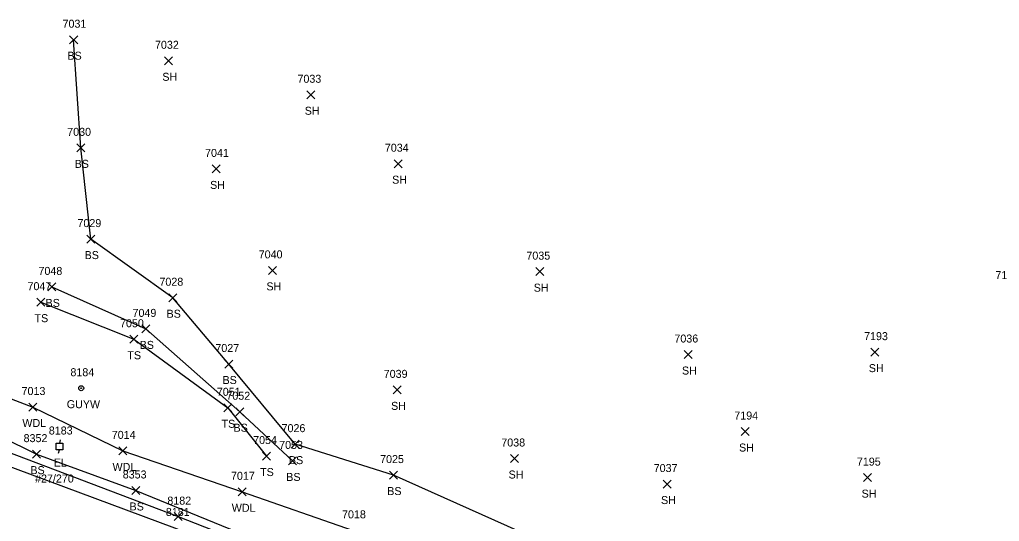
# Model space of a CAD drawing. Extents: x 1588028 to 1589597, y 137576 to 138176.
# Drawn here: x 1589205.2 to 1589450, y 137792.6 to 137918 of the extents above; entities that cross this region are included whole.
import ezdxf

# ---------------------------------------------------------------- set-up
doc = ezdxf.new("R2010")
doc.units = 0
for name, color, linetype in [('L_A', 7, 'Continuous'), ('L_I', 7, 'Continuous'), ('L_TIC', 7, 'Continuous'), ('LAWA', 7, 'Continuous'), ('LELB', 7, 'Continuous'), ('P_I', 7, 'Continuous'), ('P_TIC', 7, 'Continuous'), ('PET', 7, 'Continuous'), ('PSU', 7, 'Continuous'), ('U_A', 7, 'Continuous'), ('U_C', 7, 'Continuous'), ('U_I', 7, 'Continuous'), ('UEPT', 7, 'Continuous'), ('UPGW', 7, 'Continuous')]:
    doc.layers.add(name, color=color, linetype=linetype)

msp = doc.modelspace()

# ---------------------------------------------------------------- linework, layer by layer
at = {"layer": 'L_TIC'}
for points in [[(1589217.71, 137912.01), (1589219.71, 137914.01)], [(1589219.71, 137912.01), (1589217.71, 137914.01)], [(1589241.37, 137906.74), (1589243.37, 137908.74)], [(1589243.37, 137906.74), (1589241.37, 137908.74)], [(1589276.97, 137898.25), (1589278.97, 137900.25)], [(1589278.97, 137898.25), (1589276.97, 137900.25)], [(1589219.52, 137884.98), (1589221.52, 137886.98)], [(1589221.52, 137884.98), (1589219.52, 137886.98)], [(1589253.31, 137879.71), (1589255.31, 137881.71)], [(1589255.31, 137879.71), (1589253.31, 137881.71)], [(1589298.8, 137881.01), (1589300.8, 137883.01)], [(1589300.8, 137881.01), (1589298.8, 137883.01)], [(1589222.01, 137862.17), (1589224.01, 137864.17)], [(1589224.01, 137862.17), (1589222.01, 137864.17)], [(1589267.38, 137854.35), (1589269.38, 137856.35)], [(1589269.38, 137854.35), (1589267.38, 137856.35)], [(1589334.17, 137854.03), (1589336.17, 137856.03)], [(1589336.17, 137854.03), (1589334.17, 137856.03)], [(1589212.25, 137850.21), (1589214.25, 137852.21)], [(1589214.25, 137850.21), (1589212.25, 137852.21)], [(1589242.48, 137847.51), (1589244.48, 137849.51)], [(1589244.48, 137847.51), (1589242.48, 137849.51)], [(1589209.52, 137846.4), (1589211.52, 137848.4)], [(1589211.52, 137846.4), (1589209.52, 137848.4)], [(1589235.77, 137839.72), (1589237.77, 137841.72)], [(1589237.77, 137839.72), (1589235.77, 137841.72)], [(1589232.72, 137837.13), (1589234.72, 137839.13)], [(1589234.72, 137837.13), (1589232.72, 137839.13)], [(1589371.21, 137833.31), (1589373.21, 137835.31)], [(1589373.21, 137833.31), (1589371.21, 137835.31)], [(1589417.9, 137833.91), (1589419.9, 137835.91)], [(1589419.9, 137833.91), (1589417.9, 137835.91)], [(1589256.46, 137830.94), (1589258.46, 137832.94)], [(1589258.46, 137830.94), (1589256.46, 137832.94)], [(1589298.53, 137824.48), (1589300.53, 137826.48)], [(1589300.53, 137824.48), (1589298.53, 137826.48)], [(1589207.47, 137820.19), (1589209.47, 137822.19)], [(1589209.47, 137820.19), (1589207.47, 137822.19)], [(1589256.26, 137820), (1589258.26, 137822)], [(1589258.26, 137820), (1589256.26, 137822)], [(1589259.21, 137819.01), (1589261.21, 137821.01)], [(1589261.21, 137819.01), (1589259.21, 137821.01)], [(1589385.47, 137814.06), (1589387.47, 137816.06)], [(1589387.47, 137814.06), (1589385.47, 137816.06)], [(1589273.05, 137810.91), (1589275.05, 137812.91)], [(1589275.05, 137810.91), (1589273.05, 137812.91)], [(1589208.46, 137808.41), (1589210.46, 137810.41)], [(1589210.46, 137808.41), (1589208.46, 137810.41)], [(1589230.01, 137809.22), (1589232.01, 137811.22)], [(1589232.01, 137809.22), (1589230.01, 137811.22)], [(1589265.88, 137807.93), (1589267.88, 137809.93)], [(1589267.88, 137807.93), (1589265.88, 137809.93)], [(1589272.39, 137806.71), (1589274.39, 137808.71)], [(1589274.39, 137806.71), (1589272.39, 137808.71)], [(1589327.89, 137807.32), (1589329.89, 137809.32)], [(1589329.89, 137807.32), (1589327.89, 137809.32)], [(1589297.62, 137803.18), (1589299.62, 137805.18)], [(1589299.62, 137803.18), (1589297.62, 137805.18)], [(1589365.97, 137800.93), (1589367.97, 137802.93)], [(1589367.97, 137800.93), (1589365.97, 137802.93)], [(1589416.1, 137802.54), (1589418.1, 137804.54)], [(1589418.1, 137802.54), (1589416.1, 137804.54)], [(1589233.23, 137799.33), (1589235.23, 137801.33)], [(1589235.23, 137799.33), (1589233.23, 137801.33)], [(1589259.79, 137798.99), (1589261.79, 137800.99)], [(1589261.79, 137798.99), (1589259.79, 137800.99)]]:
    msp.add_lwpolyline(points, dxfattribs=at)
at = {"layer": 'LAWA'}
msp.add_lwpolyline([(1589191.48, 137827.66), (1589208.47, 137821.19), (1589231.01, 137810.22), (1589260.79, 137799.99), (1589288.54, 137790.36), (1589312.49, 137778.55), (1589337.68, 137767.31), (1589356.85, 137760.89), (1589388.23, 137746.7), (1589420.91, 137733.88), (1589453.12, 137717.84), (1589474.94, 137709.38)], dxfattribs=at)
at = {"layer": 'LELB'}
for points in [[(1589363.98, 137776.23), (1589339.81, 137785.78), (1589298.62, 137804.18), (1589274.05, 137811.91), (1589257.46, 137831.94), (1589243.48, 137848.51), (1589223.01, 137863.17), (1589220.52, 137885.98), (1589218.71, 137913.01)], [(1589213.25, 137851.21), (1589236.77, 137840.72), (1589260.21, 137820.01), (1589273.39, 137807.71)], [(1589210.52, 137847.4), (1589233.72, 137838.13), (1589257.26, 137821), (1589266.88, 137808.93)], [(1589158, 137835.46), (1589156.32, 137830.93), (1589175.62, 137825.43), (1589182.94, 137822.51), (1589209.46, 137809.41), (1589234.23, 137800.33), (1589267.46, 137786.74), (1589294.29, 137776.74), (1589322.35, 137767.05), (1589346.37, 137758.08), (1589352.86, 137754.06), (1589353.51, 137751.68), (1589354.61, 137751.57), (1589355.75, 137752.57)]]:
    msp.add_lwpolyline(points, dxfattribs=at)
at = {"layer": 'P_TIC'}
for points in [[(1589243.81, 137792.79), (1589245.81, 137794.79)], [(1589245.81, 137792.79), (1589243.81, 137794.79)]]:
    msp.add_lwpolyline(points, dxfattribs=at)
at = {"layer": 'PET'}
msp.add_lwpolyline([(1588976.42, 137837.98), (1588964.71, 137855.4), (1588953.74, 137871.46), (1588980.82, 137866.91), (1589021.21, 137859.55), (1589054.58, 137852.92), (1589087.36, 137843.77), (1589127.64, 137831.45), (1589150.05, 137824.37), (1589196.14, 137808.72), (1589243.87, 137790.96), (1589276.87, 137778.08), (1589322.25, 137759.62), (1589367.82, 137740.82), (1589401.87, 137726.11), (1589432.81, 137712.85), (1589459.76, 137701.46)], dxfattribs=at)
at = {"layer": 'PSU'}
msp.add_lwpolyline([(1589152.74, 137827.96), (1589197.07, 137811.88), (1589244.81, 137793.79), (1589277.33, 137781.11), (1589323.36, 137762.65), (1589353.23, 137749.52), (1589368.68, 137743.62), (1589402.84, 137728.77), (1589433.2, 137714.7), (1589460.72, 137703.44)], dxfattribs=at)
at = {"layer": 'UEPT'}
for p, q in [((1589215.36, 137812.98), (1589215.19, 137812.15)), ((1589214.36, 137810.48), (1589214.36, 137812.15)), ((1589214.36, 137812.15), (1589216.02, 137812.15)), ((1589216.02, 137810.48), (1589214.36, 137810.48)), ((1589214.94, 137809.65), (1589215.19, 137810.48)), ((1589215.19, 137811.32), (1589215.19, 137811.32)), ((1589216.02, 137812.15), (1589216.02, 137810.48))]:
    msp.add_line(p, q, dxfattribs=at)
at = {"layer": 'UPGW'}
for radius in [0.625, 0.0833]:
    msp.add_circle((1589220.59, 137825.89), radius, dxfattribs=at)

# ---------------------------------------------------------------- texts
at = {"layer": 'L_A'}
for s, p in [('BS', (1589217.15, 137908.01)), ('SH', (1589240.86, 137902.74)), ('SH', (1589276.45, 137894.25)), ('BS', (1589218.96, 137880.98)), ('SH', (1589298.29, 137877.01)), ('SH', (1589252.8, 137875.71)), ('BS', (1589221.45, 137858.17)), ('SH', (1589266.87, 137850.35)), ('SH', (1589333.66, 137850.03)), ('BS', (1589211.7, 137846.21)), ('TS', (1589208.93, 137842.4)), ('BS', (1589241.92, 137843.51)), ('BS', (1589235.21, 137835.72)), ('TS', (1589232.13, 137833.13)), ('SH', (1589417.39, 137829.91)), ('SH', (1589370.7, 137829.31)), ('BS', (1589255.9, 137826.94)), ('SH', (1589298.02, 137820.48)), ('WDL', (1589205.89, 137816.19)), ('TS', (1589255.67, 137816)), ('BS', (1589258.65, 137815.01)), ('SH', (1589384.96, 137810.06)), ('BS', (1589272.5, 137806.91)), ('BS', (1589207.9, 137804.41)), ('WDL', (1589228.42, 137805.22)), ('TS', (1589265.29, 137803.93)), ('SH', (1589327.38, 137803.32)), ('BS', (1589271.83, 137802.71)), ('BS', (1589297.06, 137799.18)), ('SH', (1589415.59, 137798.54)), ('SH', (1589365.46, 137796.93)), ('BS', (1589232.67, 137795.33)), ('WDL', (1589258.21, 137794.99))]:
    msp.add_text(s, height=2, dxfattribs=at).set_placement(p)
at = {"layer": 'L_I'}
for s, p in [('7031', (1589215.93, 137916.01)), ('7032', (1589239.03, 137910.74)), ('7033', (1589274.63, 137902.25)), ('7030', (1589217.1, 137888.98)), ('7041', (1589251.54, 137883.71)), ('7034', (1589296.46, 137885.01)), ('7029', (1589219.66, 137866.17)), ('7040', (1589264.95, 137858.35)), ('7035', (1589331.83, 137858.03)), ('7048', (1589209.92, 137854.21)), ('7192', (1589449.02, 137853.17)), ('7047', (1589207.18, 137850.4)), ('7028', (1589240.14, 137851.51)), ('7049', (1589233.42, 137843.72)), ('7050', (1589230.3, 137841.13)), ('7036', (1589368.81, 137837.31)), ('7193', (1589416.21, 137837.91)), ('7027', (1589254.12, 137834.94)), ('7039', (1589296.18, 137828.48)), ('7013', (1589205.7, 137824.19)), ('7051', (1589254.48, 137824)), ('7052', (1589256.87, 137823.01)), ('7194', (1589383.78, 137818.06)), ('7014', (1589228.23, 137813.22)), ('7026', (1589270.66, 137814.91)), ('8352', (1589206.2, 137812.41)), ('7054', (1589263.55, 137811.93)), ('7053', (1589270.05, 137810.71)), ('7038', (1589325.56, 137811.32)), ('7025', (1589295.28, 137807.18)), ('7195', (1589414.41, 137806.54)), ('8353', (1589230.97, 137803.33)), ('7017', (1589258.02, 137802.99)), ('7037', (1589363.64, 137804.93)), ('7018', (1589285.77, 137793.36))]:
    msp.add_text(s, height=2, dxfattribs=at).set_placement(p)
at = {"layer": 'P_I'}
for s, p in [('8182', (1589242.12, 137796.79)), ('8181', (1589241.75, 137793.96))]:
    msp.add_text(s, height=2, dxfattribs=at).set_placement(p)
at = {"layer": 'U_A'}
for s, p in [('GUYW', (1589216.99, 137820.89)), ('EL', (1589213.73, 137806.32))]:
    msp.add_text(s, height=2, dxfattribs=at).set_placement(p)
at = {"layer": 'U_C'}
msp.add_text('#27/270', height=2, dxfattribs=at).set_placement((1589209.07, 137802.32))
at = {"layer": 'U_I'}
for s, p in [('8184', (1589217.9, 137828.89)), ('8183', (1589212.5, 137814.32))]:
    msp.add_text(s, height=2, dxfattribs=at).set_placement(p)

doc.saveas('drawing.dxf')
